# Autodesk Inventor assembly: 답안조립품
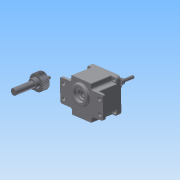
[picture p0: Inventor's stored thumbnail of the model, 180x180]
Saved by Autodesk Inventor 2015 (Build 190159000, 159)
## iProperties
Created: 2015-06
Part Number: 답안조립품
Document SubType Name: Assembly
Designer: AMC
Author: AMC
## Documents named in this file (9)
- C:\Users\AMC\Desktop\450620V1002\답안조립품.iam
- C:\Users\AMC\Desktop\450620V1002\본체.ipt
- C:\Users\AMC\Desktop\450620V1002\메인축.ipt
- C:\Users\AMC\Desktop\450620V1002\서브축.ipt
- C:\Users\AMC\Desktop\450620V1002\베어링 608.ipt
- 베어링 608.ipt
- C:\Users\AMC\Desktop\450620V1002\베어링 6003.ipt
- 베어링 6003.ipt
- C:\Users\AMC\Desktop\450620V1002\커버.ipt
